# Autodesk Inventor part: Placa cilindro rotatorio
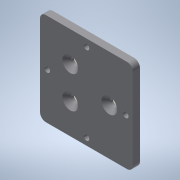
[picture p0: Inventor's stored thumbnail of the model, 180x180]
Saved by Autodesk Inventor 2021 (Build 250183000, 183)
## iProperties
Created: 2021-02
Part Number: Placa cilindro rotatorio
Material: Genérico
Document SubType Name: Modeling
Designer: ATOUZA
Density: 1 g/cm^3
Appearance: Valor por defecto
Author: ATOUZA
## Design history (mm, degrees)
node "Plano de trabajo1"
sketch "Boceto1"
  geometry: L1 (55, 32.5)-(-10, 32.5); L2 (-10, 32.5)-(-10, -32.5); L3 (-10, -32.5)-(55, -32.5); L4 (55, -32.5)-(55, 32.5); L5 (55, 32.5)-(-10, -32.5); L6 (-10, 32.5)-(55, -32.5); L7 (22.5, 22.5)-(22.5, 32.5); L8 (22.5, 16)-(22.5, -16); C1 r 2.5 at (33.814, 11.314) reference; C2 r 2.5 at (22.5, 16) reference; C3 r 2.5 at (11.186, 11.314) reference; C4 r 2.5 at (6.5, 0) reference; C5 r 2.5 at (11.186, -11.314) reference; C6 r 2.5 at (22.5, -16) reference; C7 r 2.5 at (33.814, -11.314) reference; C8 r 2.5 at (38.5, 0) reference; C9 r 2.5 at (38.5, 0); C10 r 2.5 at (11.186, 11.314); C11 r 2.5 at (11.186, -11.314); C12 r 2 at (22.5, 27.5); C13 r 2 at (-5, 0); C14 r 2 at (22.5, -27.5); C15 r 2 at (50, 0); A1 r 22.5 centre (22.5, 0) between (0, 0) and (22.5, 22.5) reference
  constraints: 16 end point, 7 centre point, 4 midpoint, 3 coincident, 3 concentric, 2 parallel, 1 horizontal, 1 perpendicular, 1 point on circle, 1 vertical, 9 other
  dimensions: "d0" = 65 distance of L3.end L2.end; "d1" = 65 distance of L2.end L1.end; "d26" = 4 diameter of C12; "d30" = 360 deg dimension on A1.centre C12.centre (derived)
extrude "Extrusión1" new body sketch "Boceto1" distance "d2" = 5; taper "d3" = 0 deg
fillet "Empalme1" dims "d4" = 4
sketch "Boceto4"
  geometry: C1 r 2.5 at (11.186, 11.314) reference; C2 r 2.5 at (11.186, -11.314) reference; C3 r 2.5 at (38.5, 0) reference; 4 further points
  constraints: 3 coincident
hole "Agujero3" sketch "Boceto4" at (11.186, 11.314), (11.186, -11.314), (38.5, 0) diameter "d19" = 5; stored, may be unused: countersink angle "d23" = 90 deg, drill point angle "d25" = 118 deg; dims "d20" = 6, "d21" = 11, "d22" = 2, "d24" = 8
node "Sólido1"
node "Referencia1"
node "Referencia2"
node "Referencia3"
node "Referencia4"
node "Referencia5"
node "Referencia6"
node "Referencia7"
node "Referencia8"
node "Referencia9"
